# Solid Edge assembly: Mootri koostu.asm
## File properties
Author: Türk
Template: Iso Assembly.asm
Last saved by: Türk
Revision: 1
Application: Solid Edge
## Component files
SILINDER.par
Silindripea.par
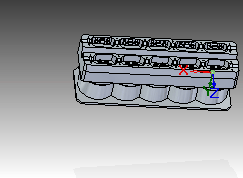
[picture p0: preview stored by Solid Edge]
